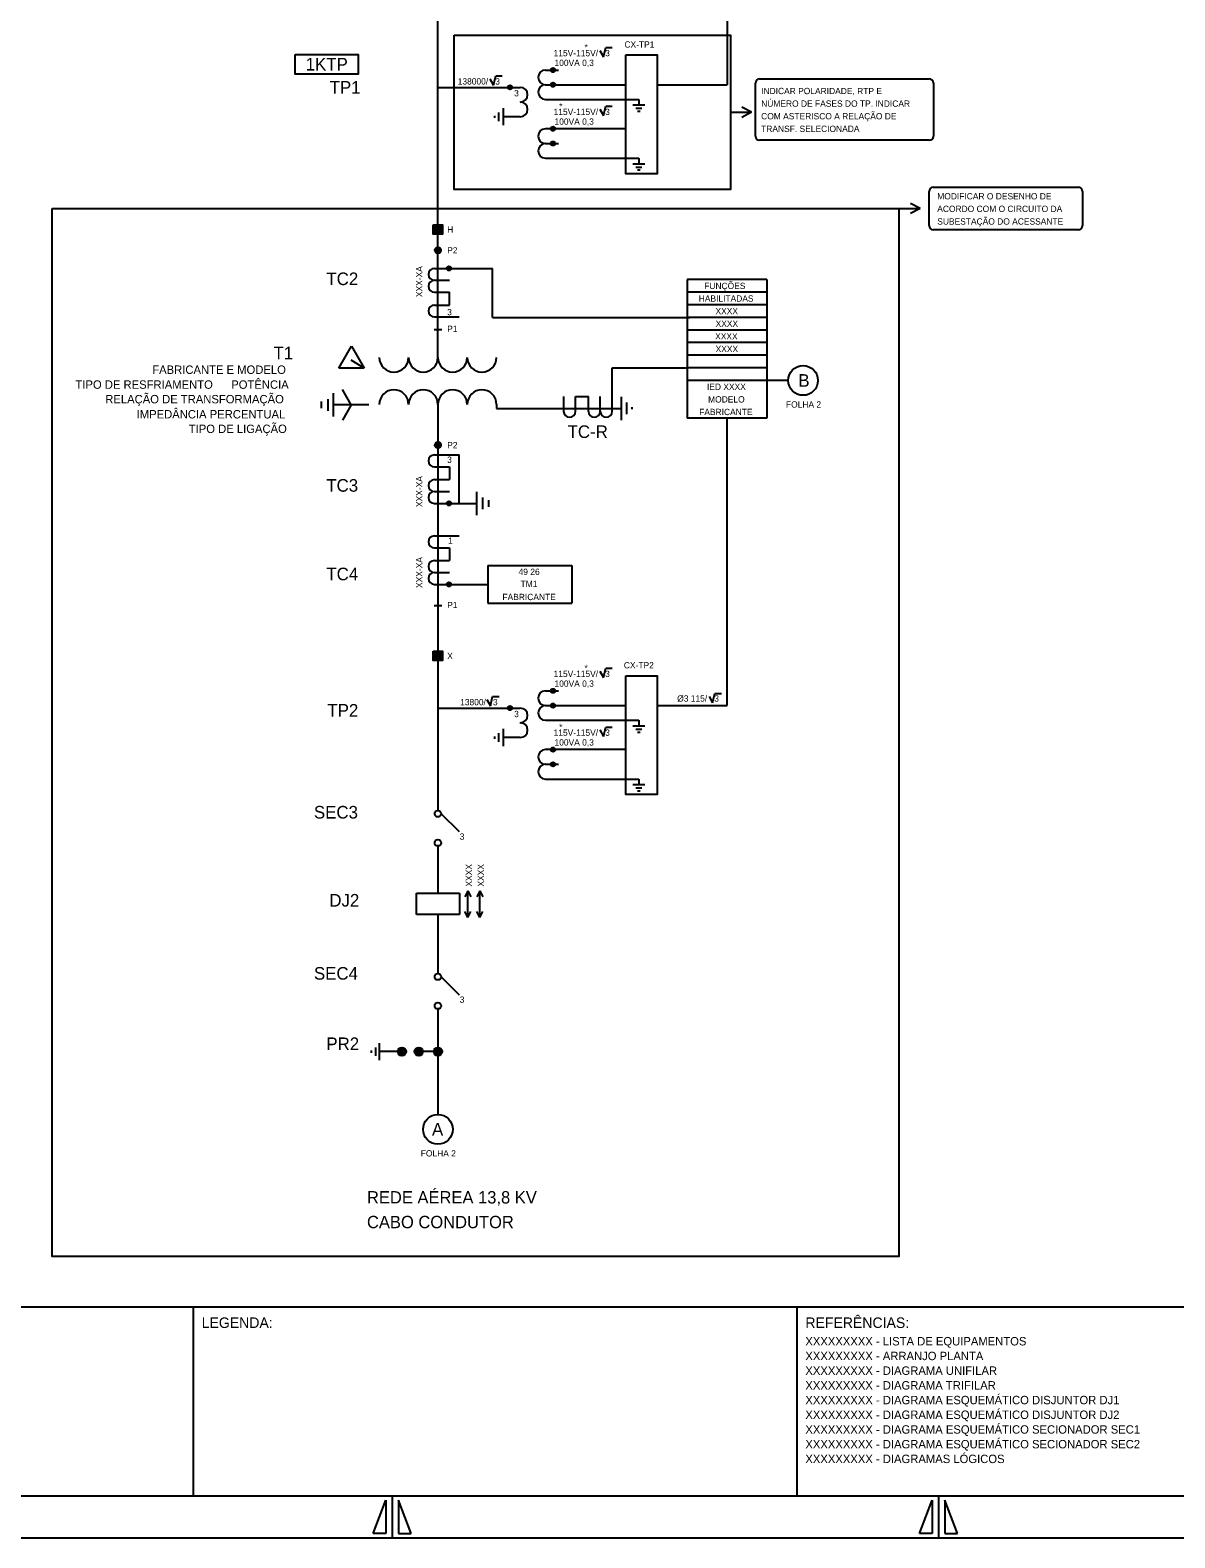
# Model space of a CAD drawing. Extents: x 563 to 1404, y 358 to 952.
# Drawn here: x 817.4 to 1089.8, y 358 to 716.8 of the extents above; entities that cross this region are included whole.
import ezdxf

# ---------------------------------------------------------------- set-up
doc = ezdxf.new("R2010")
doc.units = 0
doc.layers.add('New Level (0)', color=7, linetype='Continuous')

# ---------------------------------------------------------------- blocks, each defined once
blk = doc.blocks.new('_U3')
for p, q in [((-1.47, 0.42), (-0.62, -1.12)), ((-0.62, -1.12), (-0.07, 1.12)), ((-0.07, 1.12), (1.47, 1.12))]:
    blk.add_line(p, q)

msp = doc.modelspace()

# ---------------------------------------------------------------- linework, layer by layer
for p, q in [((914.46, 680.4), (914.46, 807.09)), ((940.06, 707.29), (943.17, 707.29)), ((940.06, 703.79), (959.19, 703.79)), ((966.67, 703.79), (983.27, 703.79)), ((914.46, 703.17), (934.06, 703.17)), ((940.06, 700.29), (962.29, 700.29)), ((962.29, 700.29), (962.29, 698.89)), ((927.93, 696.41), (927.93, 695.88)), ((928.94, 695.15), (928.94, 697.2)), ((929.96, 698.22), (929.96, 694.13)), ((934.06, 696.17), (929.96, 696.17)), ((963.69, 698.89), (960.89, 698.89)), ((961.59, 698.19), (962.99, 698.19)), ((961.94, 697.49), (962.63, 697.49)), ((959.19, 693.3), (940.06, 693.3)), ((940.06, 689.8), (943.17, 689.8)), ((940.06, 686.3), (962.29, 686.3)), ((962.29, 686.3), (962.29, 684.9)), ((963.69, 684.9), (960.89, 684.9)), ((961.59, 684.2), (962.99, 684.2)), ((961.94, 683.5), (962.63, 683.5)), ((914.46, 638.47), (914.46, 680.4)), ((913.34, 668.26), (915.49, 670.41)), ((913.34, 668.44), (915.32, 670.41)), ((913.34, 668.61), (915.14, 670.41)), ((913.34, 668.79), (914.96, 670.41)), ((913.34, 668.97), (914.79, 670.41)), ((913.34, 669.14), (914.61, 670.41)), ((913.34, 669.32), (914.43, 670.41)), ((913.34, 669.5), (914.26, 670.41)), ((913.34, 669.67), (914.08, 670.41)), ((913.34, 669.85), (913.9, 670.41)), ((913.34, 670.03), (913.73, 670.41)), ((913.34, 670.2), (913.55, 670.41)), ((913.34, 670.38), (913.37, 670.41)), ((913.46, 668.2), (915.55, 670.29)), ((913.64, 668.2), (915.55, 670.12)), ((913.81, 668.2), (915.55, 669.94)), ((913.99, 668.2), (915.55, 669.76)), ((914.17, 668.2), (915.55, 669.59)), ((914.34, 668.2), (915.55, 669.41)), ((914.52, 668.2), (915.55, 669.23)), ((914.7, 668.2), (915.55, 669.06)), ((914.87, 668.2), (915.55, 668.88)), ((915.05, 668.2), (915.55, 668.7)), ((915.23, 668.2), (915.55, 668.53)), ((915.4, 668.2), (915.55, 668.35)), ((913.64, 660.07), (927.45, 660.07)), ((913.64, 657.24), (917.18, 657.24)), ((927.45, 648.41), (927.45, 660.07)), ((973.77, 657.41), (973.77, 624.41)), ((992.76, 657.41), (973.77, 657.41)), ((992.76, 657.41), (992.76, 624.41)), ((913.64, 654.41), (917.18, 654.41)), ((917.18, 651.36), (917.18, 654.41)), ((992.76, 654.41), (973.77, 654.41)), ((913.64, 651.36), (917.18, 651.36)), ((992.76, 651.41), (973.77, 651.41)), ((913.64, 648.53), (919.51, 648.53)), ((927.45, 648.41), (974.38, 648.41)), ((992.76, 648.41), (973.77, 648.41)), ((992.76, 645.41), (973.77, 645.41)), ((992.76, 642.41), (973.77, 642.41)), ((890.88, 636.33), (893.91, 641.57)), ((893.91, 641.57), (896.93, 636.33)), ((992.76, 639.41), (973.77, 639.41)), ((992.76, 639.41), (973.77, 639.41)), ((896.93, 636.33), (890.88, 636.33)), ((896.93, 636.33), (893.84, 638.21)), ((955.93, 626.06), (955.93, 636.41)), ((955.93, 636.41), (973.77, 636.41)), ((992.76, 636.41), (973.77, 636.41)), ((997.83, 633.41), (973.77, 633.41)), ((886.77, 626.82), (886.77, 628.38)), ((888.25, 628.99), (888.25, 626.2)), ((889.65, 624.8), (889.65, 630.39)), ((893.84, 627.6), (891.75, 631.23)), ((944.39, 626.06), (944.39, 629.59)), ((947.22, 629.59), (950.27, 629.59)), ((947.22, 626.06), (947.22, 629.59)), ((950.27, 626.06), (950.27, 629.59)), ((953.1, 626.06), (953.1, 629.59)), ((958.05, 629.54), (958.05, 623.96)), ((959.44, 625.36), (959.44, 628.15)), ((898.03, 627.6), (889.65, 627.6)), ((893.84, 627.6), (891.75, 623.97)), ((928.42, 627.71), (928.42, 626.75)), ((928.42, 626.75), (958.05, 626.75)), ((960.61, 627.09), (960.61, 626.56)), ((992.76, 624.41), (973.77, 624.41)), ((983.27, 556.04), (983.27, 624.41)), ((913.64, 615.68), (919.51, 615.68)), ((913.64, 612.85), (917.18, 612.85)), ((917.18, 612.85), (917.18, 609.8)), ((913.64, 609.8), (917.18, 609.8)), ((913.64, 606.97), (917.18, 606.97)), ((923.7, 601.35), (923.7, 606.93)), ((913.64, 604.14), (917.18, 604.14)), ((917.18, 604.14), (923.7, 604.14)), ((925.09, 605.54), (925.09, 602.74)), ((926.57, 603.36), (926.57, 604.92)), ((913.64, 596.42), (919.51, 596.42)), ((913.64, 593.59), (917.18, 593.59)), ((917.18, 593.59), (917.18, 590.54)), ((913.64, 590.54), (917.18, 590.54)), ((926.38, 589.38), (926.38, 580.38)), ((926.38, 589.38), (946.37, 589.38)), ((946.37, 589.38), (946.37, 580.38)), ((913.64, 587.71), (917.18, 587.71)), ((913.64, 584.88), (926.38, 584.88)), ((913.64, 584.88), (917.18, 584.88)), ((926.38, 580.38), (946.37, 580.38)), ((913.34, 566.8), (915.49, 568.96)), ((913.34, 566.98), (915.32, 568.96)), ((913.34, 567.16), (915.14, 568.96)), ((913.34, 567.33), (914.96, 568.96)), ((913.34, 567.51), (914.79, 568.96)), ((913.34, 567.69), (914.61, 568.96)), ((913.34, 567.86), (914.43, 568.96)), ((913.34, 568.04), (914.26, 568.96)), ((913.34, 568.22), (914.08, 568.96)), ((913.34, 568.39), (913.9, 568.96)), ((913.34, 568.57), (913.73, 568.96)), ((913.34, 568.75), (913.55, 568.96)), ((913.34, 568.92), (913.37, 568.96)), ((913.46, 566.74), (915.55, 568.84)), ((913.64, 566.74), (915.55, 568.66)), ((913.81, 566.74), (915.55, 568.48)), ((913.99, 566.74), (915.55, 568.31)), ((914.17, 566.74), (915.55, 568.13)), ((914.34, 566.74), (915.55, 567.95)), ((914.52, 566.74), (915.55, 567.78)), ((914.7, 566.74), (915.55, 567.6)), ((914.87, 566.74), (915.55, 567.42)), ((915.05, 566.74), (915.55, 567.25)), ((915.23, 566.74), (915.55, 567.07)), ((915.4, 566.74), (915.55, 566.89)), ((940.06, 559.54), (943.17, 559.54)), ((914.46, 555.43), (934.06, 555.43)), ((940.06, 556.04), (959.19, 556.04)), ((966.67, 556.04), (983.27, 556.04)), ((928.94, 547.41), (928.94, 549.46)), ((929.96, 550.48), (929.96, 546.38)), ((940.06, 552.54), (962.29, 552.54)), ((963.69, 551.14), (960.89, 551.14)), ((961.59, 550.44), (962.99, 550.44)), ((961.94, 549.74), (962.63, 549.74)), ((962.29, 552.54), (962.29, 551.14)), ((927.93, 548.67), (927.93, 548.13)), ((934.06, 548.43), (929.96, 548.43)), ((959.19, 545.55), (940.06, 545.55)), ((940.06, 542.05), (943.17, 542.05)), ((940.06, 538.55), (962.29, 538.55)), ((962.29, 538.55), (962.29, 537.15)), ((963.69, 537.15), (960.89, 537.15)), ((961.59, 536.45), (962.99, 536.45)), ((961.94, 535.75), (962.63, 535.75)), ((919.56, 525.96), (915.22, 530.3)), ((909.34, 506.3), (909.34, 511.42)), ((909.34, 511.42), (919.58, 511.42)), ((919.58, 511.42), (919.58, 506.3)), ((921.58, 511.96), (920.87, 510.55)), ((921.58, 505.6), (921.58, 511.96)), ((921.58, 511.96), (922.28, 510.55)), ((924.43, 511.96), (923.72, 510.55)), ((924.43, 505.6), (924.43, 511.96)), ((924.43, 511.96), (925.13, 510.55)), ((919.58, 506.3), (909.34, 506.3)), ((921.58, 505.6), (920.87, 507.01)), ((921.58, 505.6), (922.28, 507.01)), ((924.43, 505.6), (923.72, 507.01)), ((924.43, 505.6), (925.13, 507.01)), ((919.57, 487.15), (915.23, 491.49)), ((898.57, 473.98), (898.57, 473.38)), ((898.57, 473.68), (898.57, 473.68)), ((899.57, 474.68), (899.57, 472.68)), ((900.57, 471.68), (900.57, 475.68)), ((901.89, 473.68), (900.57, 473.68)), ((905.89, 473.68), (901.89, 473.68)), ((914.47, 473.68), (909.89, 473.68))]:
    msp.add_line(p, q)
for points in [[(913.34, 670.41), (915.55, 670.41), (915.55, 668.2), (913.34, 668.2)], [(913.34, 568.96), (915.55, 568.96), (915.55, 566.74), (913.34, 566.74)]]:
    msp.add_lwpolyline(points, close=True)
for centre, radius in [((941.86, 707.29), 0.511), ((941.86, 707.29), 0.288), ((931.62, 703.17), 0.511), ((931.62, 703.17), 0.288), ((941.86, 703.79), 0.511), ((941.86, 703.79), 0.288), ((941.86, 693.3), 0.511), ((941.86, 693.3), 0.288), ((941.86, 689.8), 0.511), ((941.86, 689.8), 0.288), ((914.45, 664.41), 0.729), ((914.46, 664.4), 0.511), ((914.46, 664.4), 0.288), ((917.09, 660.07), 0.511), ((917.09, 660.07), 0.288), ((914.45, 618.04), 0.729), ((914.46, 618.04), 0.511), ((914.46, 618.04), 0.288), ((917.09, 604.14), 0.511), ((917.09, 604.14), 0.288), ((917.09, 584.88), 0.511), ((917.09, 584.88), 0.288), ((941.86, 559.54), 0.511), ((941.86, 559.54), 0.288), ((941.86, 556.04), 0.511), ((941.86, 556.04), 0.288), ((931.62, 555.43), 0.511), ((931.62, 555.43), 0.288), ((941.86, 545.55), 0.511), ((941.86, 545.55), 0.288), ((941.86, 542.05), 0.511), ((941.86, 542.05), 0.288), ((914.46, 530.3), 0.768), ((914.46, 523.39), 0.768), ((914.46, 491.49), 0.768), ((914.46, 484.59), 0.768), ((905.89, 473.68), 1), ((905.89, 473.68), 0.75), ((905.89, 473.68), 0.5), ((905.89, 473.68), 0.25), ((909.89, 473.68), 1), ((909.89, 473.68), 0.75), ((909.89, 473.68), 0.5), ((909.89, 473.68), 0.25), ((914.47, 473.68), 1), ((914.47, 473.68), 0.75), ((914.47, 473.68), 0.5), ((914.47, 473.68), 0.25)]:
    msp.add_circle(centre, radius)
for centre, radius, start, end in [((940.06, 705.54), 1.75, 90, 270), ((940.06, 702.04), 1.75, 90, 270), ((934.06, 701.42), 1.75, 270, 90), ((934.06, 697.92), 1.75, 270, 90), ((940.06, 691.55), 1.75, 90, 270), ((940.06, 688.05), 1.75, 90, 270), ((913.64, 658.66), 1.42, 90, 270), ((913.64, 655.83), 1.42, 90, 270), ((913.64, 649.94), 1.42, 90, 270), ((903.98, 638.89), 3.49, 180, 0), ((910.96, 638.89), 3.49, 180, 0), ((917.95, 638.89), 3.49, 180, 0), ((924.93, 638.89), 3.49, 180, 0), ((903.98, 627.71), 3.49, 0, 180), ((910.96, 627.71), 3.49, 0, 180), ((917.95, 627.71), 3.49, 0, 180), ((924.93, 627.71), 3.49, 0, 180), ((945.8, 626.06), 1.42, 180, 0), ((951.68, 626.06), 1.42, 180, 0), ((954.51, 626.06), 1.42, 180, 0), ((913.64, 614.27), 1.42, 90, 270), ((913.64, 608.39), 1.42, 90, 270), ((913.64, 605.56), 1.42, 90, 270), ((913.64, 595), 1.42, 90, 270), ((913.64, 589.12), 1.42, 90, 270), ((913.64, 586.29), 1.42, 90, 270), ((940.06, 557.79), 1.75, 90, 270), ((934.06, 553.68), 1.75, 270, 90), ((940.06, 554.29), 1.75, 90, 270), ((934.06, 550.18), 1.75, 270, 90), ((940.06, 543.8), 1.75, 90, 270), ((940.06, 540.3), 1.75, 90, 270)]:
    msp.add_arc(centre, radius, start, end)
at = {"layer": 'New Level (0)'}
for p, q in [((983.27, 761.45), (983.27, 703.79)), ((990.01, 691.57), (990.01, 704.16)), ((991.01, 705.16), (1031.38, 705.16)), ((1032.38, 704.16), (1032.38, 691.57)), ((984.08, 697.24), (989.11, 697.24)), ((989.11, 697.24), (986.82, 698.44)), ((989.11, 697.24), (986.82, 696.03)), ((1031.38, 690.57), (991.01, 690.57)), ((1031.36, 670.29), (1031.36, 678.4)), ((1032.36, 679.4), (1039.71, 679.4)), ((1039.71, 679.4), (1066.9, 679.4)), ((1067.9, 678.4), (1067.9, 670.29)), ((1029.2, 674.35), (1026.9, 675.55)), ((1024.17, 674.35), (1029.2, 674.35)), ((1029.2, 674.35), (1026.9, 673.14)), ((1066.9, 669.29), (1032.36, 669.29)), ((913.56, 645.57), (915.36, 645.57)), ((914.46, 627.71), (914.46, 531.07)), ((919.51, 604.14), (919.51, 615.68)), ((913.56, 579.85), (915.36, 579.85)), ((914.46, 522.63), (914.46, 511.42)), ((914.46, 506.3), (914.46, 492.26)), ((914.46, 483.82), (914.46, 458.73)), ((572.58, 412.96), (1393.58, 412.96)), ((856.24, 412.96), (856.24, 367.96)), ((999.91, 412.96), (999.91, 367.96)), ((572.58, 367.96), (1393.58, 367.96)), ((572.58, 367.96), (1393.58, 367.96)), ((899.08, 358.96), (902.08, 366.96)), ((902.08, 366.96), (902.08, 358.96)), ((903.58, 367.96), (903.58, 357.96)), ((905.08, 366.96), (905.08, 358.96)), ((908.08, 358.96), (905.08, 366.96)), ((1029.08, 358.96), (1032.08, 366.96)), ((1032.08, 366.96), (1032.08, 358.96)), ((1033.58, 367.96), (1033.58, 357.96)), ((1035.08, 366.96), (1035.08, 358.96)), ((1038.08, 358.96), (1035.08, 366.96)), ((902.08, 358.96), (899.08, 358.96)), ((905.08, 358.96), (908.08, 358.96)), ((1032.08, 358.96), (1029.08, 358.96)), ((1035.08, 358.96), (1038.08, 358.96)), ((562.58, 357.96), (1403.58, 357.96)), ((562.58, 357.96), (1403.58, 357.96))]:
    msp.add_line(p, q, dxfattribs=at)
for points in [[(918.36, 715.58), (984.08, 715.58), (984.08, 678.89), (918.36, 678.89)], [(880.5, 710.99), (895.52, 710.99), (895.52, 706.31), (880.5, 706.31)], [(959.19, 710.88), (966.67, 710.88), (966.67, 682.59), (959.19, 682.59)], [(822.69, 674.35), (1024.17, 674.35), (1024.17, 424.93), (822.69, 424.93)], [(959.19, 563.14), (966.67, 563.14), (966.67, 534.85), (959.19, 534.85)]]:
    msp.add_lwpolyline(points, close=True, dxfattribs=at)
for centre in [(1001.37, 633.41), (914.46, 455.18)]:
    msp.add_circle(centre, 3.54, dxfattribs=at)
for centre, start, end in [((991.01, 704.16), 90, 180), ((1031.38, 704.16), 0, 90), ((991.01, 691.57), 180, 270), ((1031.38, 691.57), 270, 0), ((1032.36, 678.4), 90, 180), ((1066.9, 678.4), 0, 90), ((1032.36, 670.29), 180, 270), ((1066.9, 670.29), 270, 0)]:
    msp.add_arc(centre, 1, start, end, dxfattribs=at)

# ---------------------------------------------------------------- block references
for p in [(954.49, 711.54), (928.32, 704.81), (954.49, 697.55), (954.49, 563.8), (927.56, 557.07), (980.46, 557.77), (954.49, 549.81)]:
    msp.add_blockref('_U3', p)

# ---------------------------------------------------------------- texts
for s, height, p in [('CX-TP1', 1.5, (958.85, 712.62)), ('115V-115V/   3', 1.5, (941.99, 710.57)), ('*', 1.5, (949.35, 711.99)), ('1KTP', 3, (882.98, 707.17)), ('100VA 0,3', 1.5, (942.21, 708.25)), ('TP1', 3, (888.69, 701.67)), ('138000/   3', 1.5, (919.17, 703.84)), ('3', 1.5, (932.6, 701.03)), ('NÚMERO DE FASES DO TP. INDICAR ', 1.5, (991.39, 698.55)), ('INDICAR POLARIDADE, RTP E ', 1.5, (991.39, 701.55)), ('115V-115V/   3', 1.5, (941.99, 696.58)), ('*', 1.5, (943.32, 697.94)), ('COM ASTERISCO A RELAÇÃO DE ', 1.5, (991.39, 695.55)), ('100VA 0,3', 1.5, (942.21, 694.27)), ('TRANSF. SELECIONADA', 1.5, (991.39, 692.55)), ('ACORDO COM O CIRCUITO DA ', 1.5, (1033.3, 673.5)), ('MODIFICAR O DESENHO DE ', 1.5, (1033.3, 676.5)), ('SUBESTAÇÃO DO ACESSANTE', 1.5, (1033.3, 670.5)), ('H', 1.5, (916.67, 668.56)), ('P2', 1.5, (916.67, 663.63)), ('TC2', 3, (887.92, 656.1)), ('FUNÇÕES ', 1.5, (977.84, 655.16)), ('HABILITADAS', 1.5, (976.54, 652.16)), ('3', 1.5, (916.66, 648.93)), ('XXXX', 1.5, (980.52, 649.16)), ('P1', 1.5, (916.67, 644.95)), ('XXXX', 1.5, (980.55, 646.16)), ('XXXX', 1.5, (980.45, 643.16)), ('T1', 3, (875.33, 638.44)), ('XXXX', 1.5, (980.55, 640.16)), ('FABRICANTE E MODELO', 2, (846.48, 634.97)), ('TIPO DE RESFRIAMENTO ', 2, (828.2, 631.43)), ('POTÊNCIA', 2, (865.28, 631.43)), ('IED XXXX', 1.5, (978.49, 631.16)), ('B', 3, (1000.24, 631.91)), ('RELAÇÃO DE TRANSFORMAÇÃO', 2, (835.29, 627.96)), ('MODELO', 1.5, (978.77, 628.16)), ('FOLHA 2', 1.5, (997.3, 626.95)), ('IMPEDÂNCIA PERCENTUAL', 2, (842.76, 624.37)), ('FABRICANTE', 1.5, (976.64, 625.16)), ('TIPO DE LIGAÇÃO', 2, (855.17, 620.9)), ('TC-R', 3, (945.32, 619.72)), ('P2', 1.5, (916.67, 617.27)), ('3', 1.5, (916.66, 613.8)), ('TC3', 3, (887.89, 606.93)), ('1', 1.5, (916.88, 594.53)), ('TC4', 3, (887.91, 585.85)), ('49 26', 1.5, (933.66, 587.13)), ('TM1', 1.5, (934.14, 584.24)), ('FABRICANTE', 1.5, (929.82, 581.13)), ('P1', 1.5, (916.67, 579.22)), ('X', 1.5, (916.67, 567.1)), ('115V-115V/   3', 1.5, (941.99, 562.83)), ('*', 1.5, (949.35, 564.25)), ('CX-TP2', 1.5, (958.71, 564.88)), ('100VA 0,3', 1.5, (942.21, 560.51)), ('TP2', 3, (888.16, 553.4)), ('13800/   3', 1.5, (919.75, 556.1)), ('Ø3 115/   3', 1.5, (971.41, 556.97)), ('3', 1.5, (932.6, 553.28)), ('115V-115V/   3', 1.5, (941.99, 548.84)), ('*', 1.5, (943.32, 550.2)), ('100VA 0,3', 1.5, (942.21, 546.52)), ('SEC3', 3, (884.95, 529.15)), ('3', 1.5, (919.65, 524.1)), ('DJ2', 3, (888.62, 508.19)), ('SEC4', 3, (884.96, 490.8)), ('3', 1.5, (919.66, 485.29)), ('PR2', 3, (887.91, 474.04)), ('A', 3, (913.05, 453.68)), ('FOLHA 2', 1.5, (910.38, 448.72)), ('REDE AÉREA 13,8 KV', 2.94, (897.58, 437.53)), ('CABO CONDUTOR ', 2.94, (897.58, 431.65))]:
    msp.add_text(s, height=height).set_placement(p)
for s, p in [('XXX-XA', (910.77, 653.25)), ('XXX-XA', (910.77, 603.28)), ('XXX-XA', (910.77, 584.02)), ('XXXX', (922.58, 512.96)), ('XXXX', (925.43, 512.96))]:
    msp.add_text(s, height=1.5, rotation=90).set_placement(p)
for s, height, p in [('LEGENDA:', 2.5, (858.24, 407.91)), ('REFERÊNCIAS:', 2.5, (1001.91, 407.91)), ('XXXXXXXXX - LISTA DE EQUIPAMENTOS', 2, (1001.91, 403.75)), ('XXXXXXXXX - ARRANJO PLANTA', 2, (1001.91, 400.25)), ('XXXXXXXXX - DIAGRAMA UNIFILAR', 2, (1001.91, 396.75)), ('XXXXXXXXX - DIAGRAMA TRIFILAR', 2, (1001.91, 393.25)), ('XXXXXXXXX - DIAGRAMA ESQUEMÁTICO DISJUNTOR DJ1', 2, (1001.91, 389.75)), ('XXXXXXXXX - DIAGRAMA ESQUEMÁTICO DISJUNTOR DJ2', 2, (1001.91, 386.25)), ('XXXXXXXXX - DIAGRAMA ESQUEMÁTICO SECIONADOR SEC1', 2, (1001.91, 382.75)), ('XXXXXXXXX - DIAGRAMA ESQUEMÁTICO SECIONADOR SEC2', 2, (1001.91, 379.25)), ('XXXXXXXXX - DIAGRAMAS LÓGICOS', 2, (1001.91, 375.75))]:
    msp.add_text(s, height=height, dxfattribs=at).set_placement(p)

doc.saveas('drawing.dxf')
